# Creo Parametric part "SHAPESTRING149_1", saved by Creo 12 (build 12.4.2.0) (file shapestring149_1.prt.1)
Units: Custom; MM, KILOGRAM, SECS

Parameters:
  PTC_WM_ITERATION = "0"
  PTC_WM_VERSION = "-.0"
  PTC_WM_LIFECYCLE_STATE = "In Work"
  PTC_WM_LIFECYCLE = "MO_CADDocument"
  PTC_WM_CREATED_BY = "Maximilian Roepper (Z0017RMS: MO)"
  PTC_WM_CREATED_ON = "18-Sep-26 11:36:42 AM"
  PTC_WM_MODIFIED_BY = "Maximilian Roepper (Z0017RMS: MO)"
  PTC_WM_MODIFIED_ON = "18-Sep-26 11:36:46 AM"
  PDMLINKNUMBER = "PDM000071454801"
  PTC_WM_NAME = "shapestring149_1.prt"
  PTC_WM_NUMBER = "PDM000071454801"

Other parameters: WEIGHT, WEIGHT_FACTOR, WEIGHT_ADD, _MASS_TEMP, _DIFF_TEMP, MC_ERRORS, SUPPLIER

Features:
  1. coordinate system
  2. datum plane "PRT_YZ"
  3. datum plane "PRT_XY"
  4. datum plane "PRT_XZ"
  5. coordinate system
  6. datum axis
  7. datum axis
  8. datum axis
  9. coordinate system
  10. imported feature

Other named items: PRT, SIEMENS_MO, DRW_VIEW_ORG, PRT_X, PRT_Y, PRT_Z, CS0, ROUGH_GROB

Layers: 00_STD_CSYS-KSYS, 01_STD_PLANES-EBENEN, 02_STD_AXES-ACHSEN, 03_STD_CSYS-KSYS, 24_IMPORT_FEAT-IMPORT_KE, INTFCLR

Surfaces: 1 plane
